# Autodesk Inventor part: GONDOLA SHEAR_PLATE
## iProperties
Shininess: 64.0
Length Units: 11272
Angle Units: 11279
Time Units: 11290
Mass Units: 11286
Length Display Precision: 3
Angle Display Precision: 2
Compacted: True
Part Number: GONDOLA SHEAR_PLATE
Document SubType Name: Modeling
Created: 2004-08
Designer: John Blackburn
Manufacturer: Standard
Standards Organization: Custom
Material: PVC-Piping
Density: 0.0
Volumn: 0.0
Area: 0.0
PropertySet Name: Model Information
Control State: 0
Master: False
Checked Out: False
Author: John Blackburn
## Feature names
1. ExtrusionBlind1
2. AM_HOLE_SI0029_1 [Hole]
3. AM_HOLE_SI0029_2 [Hole]
4. AM_HOLE_SI0029_3 [Hole]
5. AM_HOLE_SI0029_4 [Hole]
